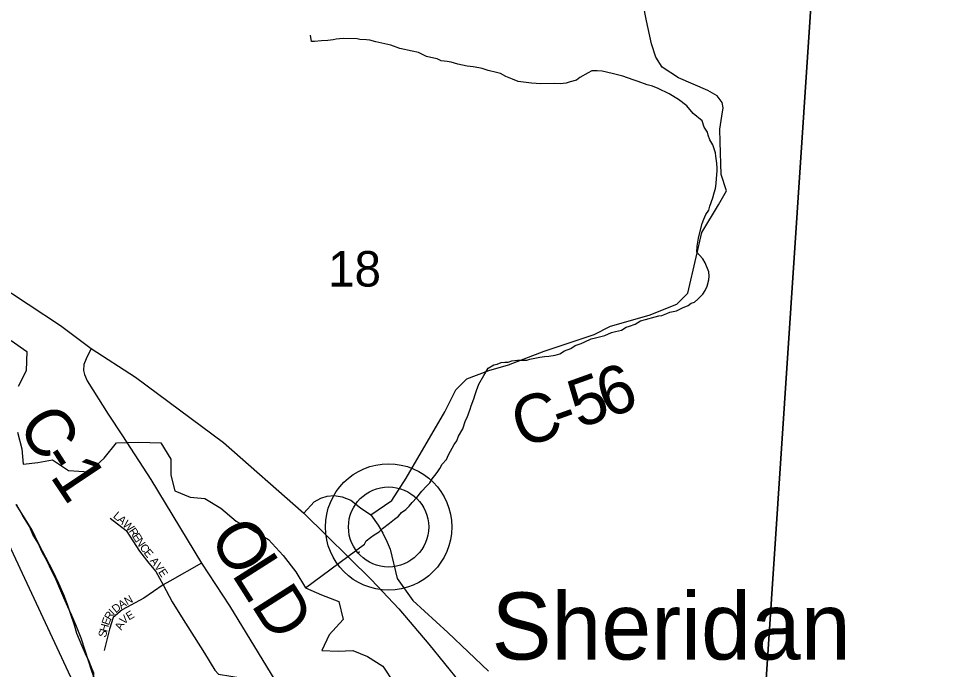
# Model space of a CAD drawing. Extents: x 1949938.81 to 1949945.61, y 152207.65 to 152214.09.
# Drawn here: x 1949939.486 to 1949940.583, y 152212.375 to 152213.141 of the extents above; entities that cross this region are included whole.
import ezdxf

# ---------------------------------------------------------------- set-up
doc = ezdxf.new("R2010")
doc.units = 0
for name, color, linetype in [('GM_X_County', 7, 'Continuous'), ('GM_X_County_Road', 7, 'Continuous'), ('GM_X_County_Road_Text', 7, 'Continuous'), ('GM_X_Major_River', 7, 'Continuous'), ('GM_X_Minor_River', 7, 'Continuous'), ('GM_X_Section', 7, 'Continuous'), ('GM_X_Section_Text', 7, 'Continuous'), ('GM_X_Township', 7, 'Continuous'), ('GM_X_Township_Subdivision', 7, 'Continuous'), ('GM_X_Township_Subdivision_Text', 7, 'Continuous'), ('GM_X_Unincorporated', 7, 'Continuous'), ('GM_X_Unincorporated_Location', 7, 'Continuous'), ('GM_X_Unincorporated_Text', 7, 'Continuous'), ('GM_X_US_Route', 7, 'Continuous')]:
    doc.layers.add(name, color=color, linetype=linetype)

msp = doc.modelspace()

# ---------------------------------------------------------------- linework, layer by layer
at = {"layer": 'GM_X_County'}
msp.add_lwpolyline([(1949938.8069, 152213.1813), (1949938.8908, 152213.14), (1949939.0267, 152213.041), (1949939.1111, 152212.9977), (1949939.166, 152212.9381), (1949939.244, 152212.8721), (1949939.3272, 152212.7909), (1949939.4464, 152212.5807), (1949939.6012, 152212.2498), (1949939.6822, 152212.0255), (1949939.7473, 152211.904), (1949939.7481, 152211.8801), (1949939.7311, 152211.8376), (1949939.7258, 152211.7457)], dxfattribs=at)
at = {"layer": 'GM_X_County_Road'}
for points in [[(1949939.9005, 152212.5567), (1949939.9255, 152212.5736), (1949939.9421, 152212.5999), (1949939.9877, 152212.678), (1949940.0007, 152212.704), (1949940.0137, 152212.717), (1949940.0397, 152212.7268), (1949940.0625, 152212.7332), (1949940.1048, 152212.7495), (1949940.1634, 152212.769), (1949940.1829, 152212.7788), (1949940.2284, 152212.7918), (1949940.2609, 152212.8048), (1949940.274, 152212.8178), (1949940.2837, 152212.8601), (1949940.2902, 152212.8893), (1949940.3098, 152212.9218), (1949940.3195, 152212.9381), (1949940.313, 152212.9576), (1949940.3121, 152212.9959), (1949940.3114, 152213.0107), (1949940.3139, 152213.0261), (1949940.3155, 152213.0358), (1949940.3143, 152213.0424), (1949940.3083, 152213.0503), (1949940.2973, 152213.0563), (1949940.2627, 152213.0714), (1949940.2438, 152213.0839), (1949940.2363, 152213.0956), (1949940.2309, 152213.1113), (1949940.225, 152213.1383), (1949940.2143, 152213.1949)], [(1949939.5712, 152212.7524), (1949939.5653, 152212.7404), (1949939.5628, 152212.7336), (1949939.5623, 152212.7265), (1949939.5636, 152212.7221), (1949939.5665, 152212.7146), (1949939.5915, 152212.6752), (1949939.6083, 152212.6496)], [(1949939.6083, 152212.6496), (1949939.6416, 152212.5985), (1949939.7012, 152212.4996), (1949939.734, 152212.4495), (1949939.7877, 152212.362), (1949939.8079, 152212.3305), (1949939.8398, 152212.2788), (1949939.8646, 152212.2394), (1949939.9224, 152212.1496), (1949939.9746, 152212.0644), (1949940.0209, 152211.9898), (1949940.0463, 152211.946), (1949940.0603, 152211.9182), (1949940.0902, 152211.8474), (1949940.1245, 152211.7264)], [(1949939.8216, 152212.5586), (1949939.8338, 152212.5719), (1949939.8417, 152212.5763), (1949939.8493, 152212.5785), (1949939.8576, 152212.5793), (1949939.8669, 152212.5778), (1949939.8772, 152212.5741), (1949939.8883, 152212.5648), (1949939.9005, 152212.5567), (1949939.9091, 152212.5444), (1949939.9147, 152212.5351), (1949939.9199, 152212.5246), (1949939.9233, 152212.5162), (1949939.9317, 152212.4817), (1949939.9502, 152212.4558), (1949939.9911, 152212.4181), (1949940.0391, 152212.3728)]]:
    msp.add_lwpolyline(points, dxfattribs=at)
at = {"layer": 'GM_X_Major_River'}
msp.add_lwpolyline([(1949939.5841, 152212.3413), (1949939.5799, 152212.3512), (1949939.5765, 152212.3607), (1949939.5723, 152212.3728), (1949939.5682, 152212.3846), (1949939.5644, 152212.3971), (1949939.5595, 152212.4115), (1949939.5534, 152212.427), (1949939.5485, 152212.438), (1949939.544, 152212.4483), (1949939.5391, 152212.4589), (1949939.5345, 152212.4699), (1949939.53, 152212.4802), (1949939.5251, 152212.4904), (1949939.5191, 152212.5029), (1949939.5138, 152212.5128), (1949939.5089, 152212.5234), (1949939.5028, 152212.5336), (1949939.4986, 152212.5431), (1949939.4907, 152212.5556), (1949939.4835, 152212.5689)], dxfattribs=at)
at = {"layer": 'GM_X_Minor_River'}
for points in [[(1949940.2845, 152212.8661), (1949940.2847, 152212.8729), (1949940.2855, 152212.8778), (1949940.2863, 152212.8824), (1949940.2876, 152212.8877), (1949940.2908, 152212.8997), (1949940.2928, 152212.9047), (1949940.2952, 152212.9103), (1949940.2987, 152212.9156), (1949940.2999, 152212.9201), (1949940.3031, 152212.9299), (1949940.3047, 152212.936), (1949940.3063, 152212.9409), (1949940.3072, 152212.9469), (1949940.3077, 152212.9526), (1949940.3082, 152212.9617), (1949940.3083, 152212.9651), (1949940.308, 152212.9708), (1949940.307, 152212.9792), (1949940.3063, 152212.983), (1949940.3031, 152212.9926), (1949940.2997, 152212.9983), (1949940.2976, 152213.0037), (1949940.2969, 152213.0075), (1949940.2932, 152213.0132), (1949940.2907, 152213.0205), (1949940.2802, 152213.0294), (1949940.2728, 152213.0383), (1949940.2627, 152213.0457), (1949940.2518, 152213.0523), (1949940.2391, 152213.0586), (1949940.2323, 152213.0614), (1949940.2259, 152213.063), (1949940.2154, 152213.067), (1949940.2093, 152213.069), (1949940.1973, 152213.0733), (1949940.1909, 152213.075), (1949940.1848, 152213.0766), (1949940.1728, 152213.0791), (1949940.1671, 152213.0796), (1949940.161, 152213.0797), (1949940.1564, 152213.0771), (1949940.1465, 152213.0716), (1949940.1427, 152213.0686), (1949940.1354, 152213.0664), (1949940.1305, 152213.065), (1949940.1236, 152213.0643), (1949940.1172, 152213.0645), (1949940.1009, 152213.0644), (1949940.0896, 152213.0649), (1949940.0835, 152213.0658), (1949940.0741, 152213.0671), (1949940.0673, 152213.0699), (1949940.0594, 152213.073), (1949940.0534, 152213.0766), (1949940.0485, 152213.0774), (1949940.0387, 152213.0798), (1949940.0315, 152213.0822), (1949940.0278, 152213.0831), (1949940.021, 152213.0843), (1949940.0142, 152213.0852), (1949940.0032, 152213.0873), (1949939.9953, 152213.0897), (1949939.9904, 152213.0905), (1949939.9836, 152213.0914), (1949939.9787, 152213.0938), (1949939.9746, 152213.0946), (1949939.9663, 152213.0966), (1949939.9569, 152213.101), (1949939.9493, 152213.1026), (1949939.9346, 152213.1059), (1949939.9241, 152213.1099), (1949939.9169, 152213.1115), (1949939.9063, 152213.1136), (1949939.8996, 152213.1156), (1949939.8954, 152213.1161), (1949939.8878, 152213.1166), (1949939.8844, 152213.1174), (1949939.8689, 152213.1177), (1949939.8636, 152213.1174), (1949939.8598, 152213.1167), (1949939.8564, 152213.116), (1949939.8499, 152213.1153), (1949939.8427, 152213.1147), (1949939.8344, 152213.1141), (1949939.8306, 152213.1141), (1949939.8296, 152213.1214)], [(1949939.8238, 152212.4708), (1949939.8933, 152212.5222), (1949939.8952, 152212.526), (1949939.9002, 152212.5301), (1949939.9045, 152212.5331), (1949939.9106, 152212.5368), (1949939.9144, 152212.5405), (1949939.9225, 152212.5468), (1949939.9283, 152212.5517), (1949939.9332, 152212.555), (1949939.9367, 152212.5595), (1949939.9417, 152212.5628), (1949939.9456, 152212.5669), (1949939.9491, 152212.5714), (1949939.9548, 152212.577), (1949939.9607, 152212.5845), (1949939.9661, 152212.5905), (1949939.9699, 152212.5942), (1949939.973, 152212.5991), (1949939.9761, 152212.6032), (1949939.9788, 152212.6066), (1949939.982, 152212.6111), (1949939.9847, 152212.6164), (1949939.9897, 152212.622), (1949939.9921, 152212.6273), (1949939.9987, 152212.6397), (1949940.0019, 152212.6438), (1949940.0038, 152212.6495), (1949940.0089, 152212.6581), (1949940.0121, 152212.6679), (1949940.0141, 152212.6713), (1949940.0177, 152212.6811), (1949940.0189, 152212.6849), (1949940.0217, 152212.6932), (1949940.0236, 152212.6985), (1949940.0252, 152212.703), (1949940.0276, 152212.7106), (1949940.0335, 152212.7207), (1949940.0386, 152212.7294), (1949940.0455, 152212.7334), (1949940.0493, 152212.7341), (1949940.0542, 152212.7359), (1949940.0584, 152212.7366), (1949940.0622, 152212.7366), (1949940.0668, 152212.738), (1949940.0732, 152212.7387), (1949940.0785, 152212.7389), (1949940.0842, 152212.7389), (1949940.088, 152212.7399), (1949940.0994, 152212.7424), (1949940.1051, 152212.7431), (1949940.11, 152212.7437), (1949940.1176, 152212.7447), (1949940.123, 152212.7462), (1949940.1287, 152212.7499), (1949940.136, 152212.7524), (1949940.1413, 152212.7561), (1949940.1482, 152212.7586), (1949940.1524, 152212.7605), (1949940.16, 152212.7638), (1949940.165, 152212.7652), (1949940.176, 152212.768), (1949940.184, 152212.7713), (1949940.1886, 152212.7724), (1949940.1958, 152212.7742), (1949940.2012, 152212.7775), (1949940.205, 152212.7789), (1949940.2118, 152212.7811), (1949940.2183, 152212.7852), (1949940.2241, 152212.7866), (1949940.2355, 152212.7898), (1949940.2397, 152212.7909), (1949940.2431, 152212.7916), (1949940.2492, 152212.7938), (1949940.2526, 152212.7952), (1949940.2606, 152212.797), (1949940.2675, 152212.8003), (1949940.2743, 152212.8032), (1949940.2778, 152212.8058), (1949940.2816, 152212.8073), (1949940.2858, 152212.8106), (1949940.2916, 152212.8166), (1949940.2943, 152212.8207), (1949940.2967, 152212.826), (1949940.2987, 152212.8335), (1949940.2988, 152212.8377), (1949940.2985, 152212.843), (1949940.2942, 152212.8534), (1949940.2916, 152212.8583), (1949940.2875, 152212.8626), (1949940.2845, 152212.8661)], [(1949939.4773, 152212.762), (1949939.4954, 152212.749), (1949939.4946, 152212.7262), (1949939.4854, 152212.708)], [(1949939.4844, 152212.6542), (1949939.4896, 152212.6344), (1949939.4911, 152212.6162), (1949939.5085, 152212.6184), (1949939.5259, 152212.6214), (1949939.5448, 152212.6091), (1949939.569, 152212.6075), (1949939.5865, 152212.6234), (1949939.601, 152212.6416), (1949939.6275, 152212.6422), (1949939.6532, 152212.6414), (1949939.6653, 152212.6224), (1949939.6652, 152212.6034), (1949939.6697, 152212.5851), (1949939.6878, 152212.5775), (1949939.7052, 152212.5759), (1949939.7241, 152212.5645), (1949939.7422, 152212.5492), (1949939.7626, 152212.5377), (1949939.78, 152212.5278), (1949939.7973, 152212.5088), (1949939.8124, 152212.4897), (1949939.8237, 152212.4707), (1949939.8426, 152212.4623), (1949939.863, 152212.4546), (1949939.8682, 152212.4333), (1949939.8515, 152212.4152), (1949939.8431, 152212.397), (1949939.862, 152212.3962), (1949939.8794, 152212.3969), (1949939.8968, 152212.39), (1949939.9149, 152212.3785), (1949939.9277, 152212.3587)], [(1949939.885, 152212.5114), (1949939.8871, 152212.5136)]]:
    msp.add_lwpolyline(points, dxfattribs=at)
at = {"layer": 'GM_X_Section'}
msp.add_lwpolyline([(1949940.4294, 152213.3146), (1949940.3609, 152212.2864), (1949939.5717, 152212.3312), (1949939.5744, 152212.3703), (1949939.5718, 152212.3771), (1949939.5691, 152212.3839), (1949939.5646, 152212.393), (1949939.5608, 152212.4021), (1949939.5544, 152212.4169), (1949939.5517, 152212.4267), (1949939.5472, 152212.4392), (1949939.5434, 152212.451), (1949939.5392, 152212.4624), (1949939.5332, 152212.476), (1949939.526, 152212.4908), (1949939.5139, 152212.5139), (1949939.5052, 152212.531), (1949939.5018, 152212.5385), (1949939.4938, 152212.5518), (1949939.4832, 152212.5689)], dxfattribs=at)
msp.add_lwpolyline([(1949941.5133, 152213.2491), (1949941.4524, 152212.2232), (1949940.3609, 152212.2864), (1949940.4294, 152213.3146)], close=True, dxfattribs=at)
at = {"layer": 'GM_X_Township'}
msp.add_lwpolyline([(1949938.8069, 152213.1813), (1949938.8908, 152213.14), (1949939.0267, 152213.041), (1949939.1111, 152212.9977), (1949939.166, 152212.9381), (1949939.244, 152212.8721), (1949939.3272, 152212.7909), (1949939.4464, 152212.5807), (1949939.6012, 152212.2498), (1949939.6822, 152212.0255), (1949939.7473, 152211.904), (1949939.7481, 152211.8801), (1949939.7311, 152211.8376), (1949939.7258, 152211.7457)], dxfattribs=at)
at = {"layer": 'GM_X_Township_Subdivision'}
for points in [[(1949939.5935, 152212.5526), (1949939.6126, 152212.5382), (1949939.6283, 152212.514), (1949939.6392, 152212.4996), (1949939.6473, 152212.4901), (1949939.6559, 152212.4742), (1949939.6666, 152212.4544), (1949939.6776, 152212.4365), (1949939.7049, 152212.3939), (1949939.7169, 152212.3737), (1949939.7214, 152212.3689), (1949939.7501, 152212.3643), (1949939.7668, 152212.3617), (1949939.7877, 152212.362)], [(1949939.7012, 152212.4996), (1949939.6639, 152212.4787)], [(1949939.6639, 152212.4787), (1949939.6559, 152212.4742), (1949939.6334, 152212.4586), (1949939.6079, 152212.4447), (1949939.5972, 152212.4359), (1949939.5928, 152212.4221), (1949939.5865, 152212.397)]]:
    msp.add_lwpolyline(points, dxfattribs=at)
at = {"layer": 'GM_X_Unincorporated'}
for radius in [0.0744, 0.0472]:
    msp.add_circle((1949939.9215, 152212.5424), radius, dxfattribs=at)
at = {"layer": 'GM_X_Unincorporated_Location'}
msp.add_line((1949939.9215, 152212.5424), (1949939.9215, 152212.5424), dxfattribs=at)
at = {"layer": 'GM_X_US_Route'}
for points in [[(1949938.8069, 152213.2746), (1949938.8368, 152213.2545), (1949938.9951, 152213.1414), (1949939.189, 152213.0058), (1949939.4205, 152212.855), (1949939.5354, 152212.7798), (1949939.5633, 152212.7584)], [(1949939.5633, 152212.7584), (1949939.5712, 152212.7524), (1949939.6236, 152212.7189), (1949939.7271, 152212.6418), (1949939.8216, 152212.5586), (1949939.9015, 152212.4802), (1949939.9335, 152212.446), (1949939.9688, 152212.4043), (1949940.0056, 152212.3587), (1949940.0227, 152212.3356), (1949940.0559, 152212.2881)]]:
    msp.add_lwpolyline(points, dxfattribs=at)

# ---------------------------------------------------------------- texts
at = {"layer": 'GM_X_County_Road_Text'}
for s, rotation, p in [('6', 19.8238, (1949940.1787, 152212.6698)), ('5', 19.7675, (1949940.1457, 152212.658)), ('C', 18.2134, (1949940.0778, 152212.635)), ('C', 302.372, (1949939.4836, 152212.6627)), ('-', 19.6378, (1949940.1236, 152212.6501)), ('-', 302.7063, (1949939.5087, 152212.6229)), ('1', 303.7976, (1949939.522, 152212.6023)), ('O', 301.0729, (1949939.7092, 152212.531)), ('L', 302.4533, (1949939.7358, 152212.4869)), ('D', 302.5044, (1949939.7587, 152212.451))]:
    msp.add_text(s, height=0.0568, rotation=rotation, dxfattribs=at).set_placement(p)
at = {"layer": 'GM_X_Section_Text'}
msp.add_text('18', height=0.04186, rotation=0, dxfattribs=at).set_placement((1949939.8503, 152212.8255))
at = {"layer": 'GM_X_Township_Subdivision_Text'}
for s, rotation, p in [('L', 319.2176, (1949939.5964, 152212.5543)), ('A', 319.2171, (1949939.6015, 152212.55)), ('W', 315.3938, (1949939.6077, 152212.5446)), ('R', 304.5792, (1949939.6151, 152212.5374)), ('E', 303.3207, (1949939.6193, 152212.5313)), ('N', 303.3436, (1949939.623, 152212.5257)), ('C', 306.1556, (1949939.6279, 152212.5183)), ('E', 309.7107, (1949939.6327, 152212.5117)), ('A', 307.4786, (1949939.64, 152212.5024)), ('V', 306.1174, (1949939.6451, 152212.4958)), ('E', 303.9401, (1949939.6499, 152212.4892)), ('N', 29.7757, (1949939.6136, 152212.45)), ('D', 39.0122, (1949939.6003, 152212.4406)), ('A', 31.7969, (1949939.6066, 152212.4456)), ('R', 59.2866, (1949939.5942, 152212.4318)), ('I', 45.3593, (1949939.5976, 152212.4378)), ('E', 31.1019, (1949939.6158, 152212.4322)), ('E', 70.9354, (1949939.5922, 152212.426)), ('V', 41.0831, (1949939.6099, 152212.427)), ('S', 76.8807, (1949939.5886, 152212.4117)), ('H', 74.7835, (1949939.5901, 152212.4181)), ('A', 65.4073, (1949939.6071, 152212.4203))]:
    msp.add_text(s, height=0.00947, rotation=rotation, dxfattribs=at).set_placement(p)
at = {"layer": 'GM_X_Unincorporated_Text'}
msp.add_text('Sheridan', height=0.07898, rotation=0, dxfattribs=at).set_placement((1949940.0428, 152212.3863))

doc.saveas('drawing.dxf')
